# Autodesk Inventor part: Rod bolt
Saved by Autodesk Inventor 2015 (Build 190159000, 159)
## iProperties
Created: 2015-04
Part Number: Rod bolt
Material: Generic
Document SubType Name: Modeling
Designer: Gabriel Cabellos
Density: 1 g/cm^3
Appearance: Default
Author: Gabriel Cabellos
Sending System: SolidWorks 2011
Last Author: Pets
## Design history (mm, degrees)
node "Rod bolt.ipt1"
node "CirPattern1"
node "Base1"
